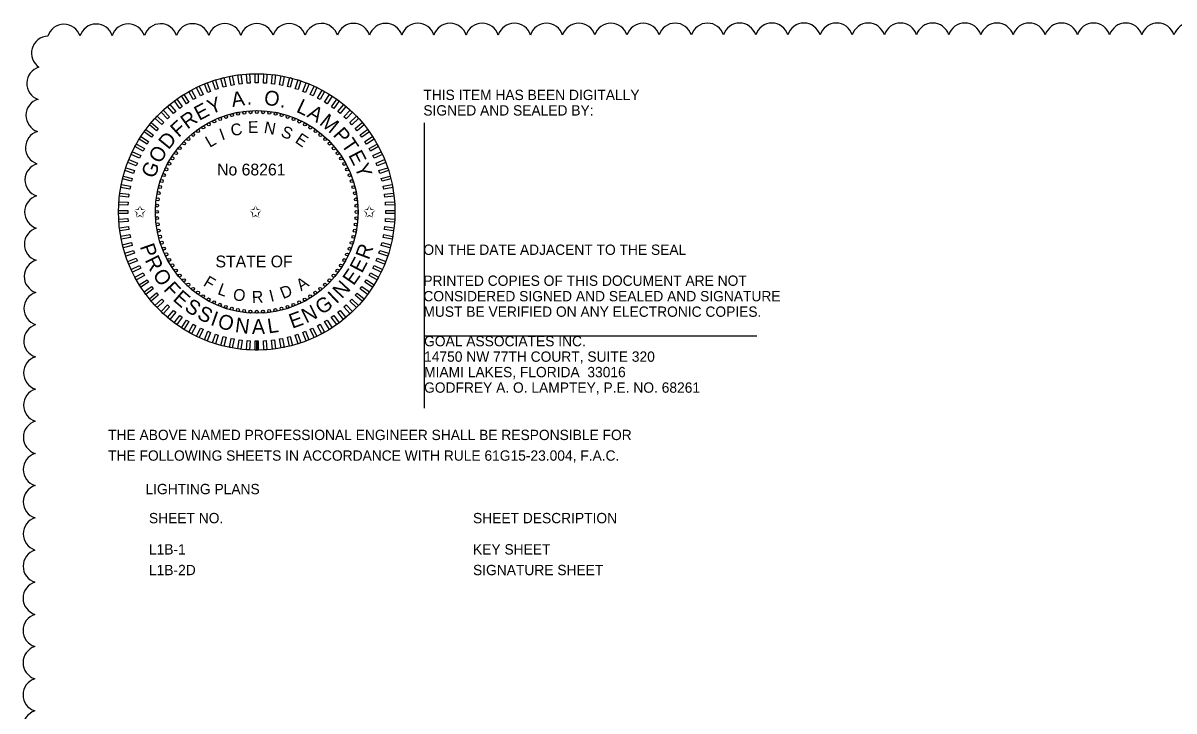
# Model space of a CAD drawing. Extents: x -811.2 to -795, y -2307.6 to -2235.1.
# Drawn here: x -811.08 to -803.27, y -2289.48 to -2284.82 of the extents above; entities that cross this region are included whole.
import ezdxf

# ---------------------------------------------------------------- set-up
doc = ezdxf.new("R2010")
doc.units = 0
for name, color, linetype in [('AdhocPoint_dp', 7, 'Continuous'), ('Cloud_dp', 7, 'Continuous'), ('Logo_dp', 7, 'Continuous'), ('TeleMisc', 7, 'Continuous'), ('TextDetails', 7, 'Continuous'), ('TextMisc', 7, 'Continuous')]:
    doc.layers.add(name, color=color, linetype=linetype)

msp = doc.modelspace()

# ---------------------------------------------------------------- linework, layer by layer
at = {"layer": 'AdhocPoint_dp'}
for p, q in [((-808.3546, -2285.4958), (-808.3546, -2287.4306)), ((-808.3546, -2286.9406), (-806.0979, -2286.9406))]:
    msp.add_line(p, q, dxfattribs=at)
at = {"layer": 'Cloud_dp'}
for centre, radius, start, end in [((-810.7982, -2284.9413), 0.1145, 18.05658, 163.05658), ((-810.58, -2284.9396), 0.1145, 17.79982, 162.79982), ((-810.3617, -2284.9386), 0.1145, 17.71875, 162.71875), ((-810.1434, -2284.9379), 0.1145, 17.67426, 162.67426), ((-809.9251, -2284.9373), 0.1145, 17.64508, 162.64508), ((-809.7068, -2284.9368), 0.1145, 17.62402, 162.62402), ((-809.4885, -2284.9363), 0.1145, 17.60791, 162.60791), ((-809.2701, -2284.9359), 0.1145, 17.59506, 162.59506), ((-809.0518, -2284.9356), 0.1145, 17.5845, 162.5845), ((-808.8335, -2284.9353), 0.1145, 17.57563, 162.57563), ((-808.6152, -2284.935), 0.1145, 17.56803, 162.56803), ((-808.3969, -2284.9348), 0.1145, 17.56143, 162.56143), ((-808.1786, -2284.9345), 0.1145, 17.55563, 162.55563), ((-807.9602, -2284.9343), 0.1145, 17.55047, 162.55047), ((-807.7419, -2284.9342), 0.1145, 17.54585, 162.54585), ((-807.5236, -2284.934), 0.1145, 17.54168, 162.54168), ((-807.3053, -2284.9338), 0.1145, 17.53789, 162.53789), ((-807.087, -2284.9337), 0.1145, 17.53443, 162.53443), ((-806.8686, -2284.9336), 0.1145, 17.53125, 162.53125), ((-806.6503, -2284.9335), 0.1145, 17.52832, 162.52832), ((-806.432, -2284.9334), 0.1145, 17.52559, 162.52559), ((-806.2137, -2284.9333), 0.1145, 17.52306, 162.52306), ((-805.9953, -2284.9332), 0.1145, 17.5207, 162.5207), ((-805.777, -2284.9331), 0.1145, 17.51849, 162.51849), ((-805.5587, -2284.933), 0.1145, 17.51642, 162.51642), ((-805.3404, -2284.933), 0.1145, 17.51447, 162.51447), ((-805.1221, -2284.9329), 0.1145, 17.51263, 162.51263), ((-804.9037, -2284.9329), 0.1145, 17.51089, 162.51089), ((-804.6854, -2284.9329), 0.1145, 17.50924, 162.50924), ((-804.4671, -2284.9328), 0.1145, 17.50767, 162.50767), ((-804.2488, -2284.9328), 0.1145, 17.50619, 162.50619), ((-804.0304, -2284.9328), 0.1145, 17.50477, 162.50477), ((-803.8121, -2284.9328), 0.1145, 17.50342, 162.50342), ((-803.5938, -2284.9327), 0.1145, 17.50213, 162.50213), ((-803.3755, -2284.9327), 0.1145, 17.5009, 162.5009), ((-803.1571, -2284.9327), 0.1145, 17.50004, 162.50004), ((-810.9047, -2285.0222), 0.1144, 91.47713, 236.47713), ((-810.9365, -2285.2277), 0.1145, 105.90805, 250.90805), ((-810.9416, -2285.4456), 0.1145, 106.41676, 251.41676), ((-810.9452, -2285.6638), 0.1145, 106.67623, 251.67623), ((-810.9481, -2285.882), 0.1145, 106.84098, 251.84098), ((-810.9504, -2286.1002), 0.1145, 106.95758, 251.95758), ((-810.9523, -2286.3185), 0.1145, 107.04572, 252.04572), ((-810.9539, -2286.5368), 0.1145, 107.11538, 252.11538), ((-810.9552, -2286.755), 0.1145, 107.17224, 252.17224), ((-810.9564, -2286.9733), 0.1145, 107.21979, 252.21979), ((-810.9574, -2287.1916), 0.1145, 107.26033, 252.26033), ((-810.9582, -2287.4099), 0.1145, 107.29543, 252.29543), ((-810.9589, -2287.6282), 0.1145, 107.3262, 252.3262), ((-810.9595, -2287.8465), 0.1145, 107.35348, 252.35348), ((-810.96, -2288.0649), 0.1145, 107.37786, 252.37786), ((-810.9605, -2288.2832), 0.1145, 107.39984, 252.39984), ((-810.9608, -2288.5015), 0.1145, 107.41978, 252.41978), ((-810.9611, -2288.7198), 0.1145, 107.43798, 252.43798), ((-810.9613, -2288.9381), 0.1145, 107.45468, 252.45468), ((-810.9614, -2289.1564), 0.1145, 107.47007, 252.47007), ((-810.9615, -2289.3747), 0.1145, 107.48432, 252.48432), ((-810.9616, -2289.593), 0.1145, 107.49902, 252.49902)]:
    msp.add_arc(centre, radius, start, end, dxfattribs=at)
at = {"layer": 'TextDetails'}
for radius in [0.9375, 0.6875]:
    msp.add_circle((-809.4901, -2286.0992), radius, dxfattribs=at)
at = {"layer": 'TextMisc'}
for p, q in [((-809.5001, -2287.0368), (-809.5003, -2286.9743)), ((-809.4901, -2287.0367), (-809.4903, -2286.9742)), ((-809.4801, -2287.0367), (-809.4803, -2286.9742))]:
    msp.add_line(p, q, dxfattribs=at)
for points in [[(-809.6979, -2285.2492), (-809.7174, -2285.2542), (-809.7329, -2285.1937), (-809.7134, -2285.1887)], [(-809.6441, -2285.2378), (-809.6639, -2285.2416), (-809.6756, -2285.1803), (-809.6558, -2285.1765)], [(-809.5897, -2285.2298), (-809.6097, -2285.2324), (-809.6175, -2285.1704), (-809.5975, -2285.1679)], [(-809.5349, -2285.2253), (-809.555, -2285.2266), (-809.559, -2285.1643), (-809.5388, -2285.163)], [(-809.4799, -2285.2242), (-809.5001, -2285.2242), (-809.5001, -2285.1618), (-809.4799, -2285.1618)], [(-809.425, -2285.2266), (-809.4452, -2285.2253), (-809.4412, -2285.163), (-809.4211, -2285.1643)], [(-809.3703, -2285.2324), (-809.3904, -2285.2299), (-809.3825, -2285.1679), (-809.3625, -2285.1704)], [(-809.3162, -2285.2416), (-809.336, -2285.2378), (-809.3243, -2285.1765), (-809.3045, -2285.1803)], [(-809.2626, -2285.2542), (-809.2822, -2285.2492), (-809.2667, -2285.1887), (-809.2471, -2285.1938)], [(-809.9027, -2285.3275), (-809.9204, -2285.3373), (-809.9505, -2285.2826), (-809.9328, -2285.2728)], [(-809.8535, -2285.3032), (-809.8717, -2285.3118), (-809.8983, -2285.2553), (-809.8801, -2285.2467)], [(-809.8028, -2285.2819), (-809.8215, -2285.2893), (-809.8445, -2285.2313), (-809.8258, -2285.2239)], [(-809.7508, -2285.2639), (-809.77, -2285.2701), (-809.7893, -2285.2108), (-809.7701, -2285.2045)], [(-809.21, -2285.2702), (-809.2292, -2285.264), (-809.2099, -2285.2046), (-809.1907, -2285.2108)], [(-809.1585, -2285.2894), (-809.1773, -2285.282), (-809.1543, -2285.2239), (-809.1355, -2285.2314)], [(-809.1083, -2285.3118), (-809.1266, -2285.3032), (-809.1, -2285.2467), (-809.0817, -2285.2553)], [(-809.0596, -2285.3374), (-809.0773, -2285.3276), (-809.0473, -2285.2729), (-809.0296, -2285.2826)], [(-809.9962, -2285.3853), (-810.0125, -2285.3972), (-810.0492, -2285.3467), (-810.0329, -2285.3348)], [(-809.9504, -2285.355), (-809.9674, -2285.3658), (-810.0009, -2285.3131), (-809.9838, -2285.3023)], [(-809.0127, -2285.3659), (-809.0297, -2285.3551), (-808.9962, -2285.3024), (-808.9792, -2285.3132)], [(-808.9676, -2285.3973), (-808.9839, -2285.3855), (-808.9472, -2285.3349), (-808.9308, -2285.3468)], [(-810.0817, -2285.4544), (-810.0964, -2285.4682), (-810.1392, -2285.4227), (-810.1244, -2285.4089)], [(-810.04, -2285.4185), (-810.0556, -2285.4314), (-810.0954, -2285.3833), (-810.0798, -2285.3704)], [(-808.9245, -2285.4315), (-808.9401, -2285.4187), (-808.9003, -2285.3705), (-808.8847, -2285.3834)], [(-808.8837, -2285.4684), (-808.8984, -2285.4545), (-808.8557, -2285.409), (-808.841, -2285.4228)], [(-810.1579, -2285.5336), (-810.1707, -2285.5492), (-810.2188, -2285.5094), (-810.206, -2285.4938)], [(-810.121, -2285.4928), (-810.1348, -2285.5075), (-810.1804, -2285.4648), (-810.1665, -2285.4501)], [(-808.8453, -2285.5077), (-808.8591, -2285.493), (-808.8136, -2285.4502), (-808.7998, -2285.4649)], [(-808.8094, -2285.5493), (-808.8223, -2285.5338), (-808.7742, -2285.494), (-808.7613, -2285.5095)], [(-810.192, -2285.5767), (-810.2039, -2285.593), (-810.2544, -2285.5563), (-810.2426, -2285.54)], [(-808.7762, -2285.5932), (-808.7881, -2285.5768), (-808.7376, -2285.5401), (-808.7257, -2285.5565)], [(-810.252, -2285.6688), (-810.2617, -2285.6865), (-810.3164, -2285.6564), (-810.3067, -2285.6387)], [(-810.2235, -2285.6218), (-810.2343, -2285.6388), (-810.287, -2285.6054), (-810.2762, -2285.5883)], [(-808.7459, -2285.639), (-808.7567, -2285.6219), (-808.7039, -2285.5885), (-808.6931, -2285.6055)], [(-808.7184, -2285.6866), (-808.7281, -2285.6689), (-808.6734, -2285.6389), (-808.6637, -2285.6565)], [(-810.2775, -2285.7175), (-810.2861, -2285.7357), (-810.3426, -2285.7091), (-810.334, -2285.6909)], [(-808.694, -2285.7359), (-808.7026, -2285.7176), (-808.6461, -2285.691), (-808.6375, -2285.7093)], [(-810.3192, -2285.8192), (-810.3254, -2285.8384), (-810.3848, -2285.8191), (-810.3786, -2285.7999)], [(-810.3, -2285.7677), (-810.3074, -2285.7864), (-810.3654, -2285.7634), (-810.358, -2285.7447)], [(-808.6728, -2285.7866), (-808.6802, -2285.7678), (-808.6222, -2285.7448), (-808.6147, -2285.7636)], [(-808.6548, -2285.8385), (-808.661, -2285.8193), (-808.6016, -2285.8), (-808.5954, -2285.8192)], [(-810.3351, -2285.8718), (-810.3401, -2285.8913), (-810.4006, -2285.8758), (-810.3956, -2285.8562)], [(-808.64, -2285.8915), (-808.6451, -2285.872), (-808.5846, -2285.8564), (-808.5796, -2285.876)], [(-810.357, -2285.9795), (-810.3595, -2285.9995), (-810.4215, -2285.9917), (-810.4189, -2285.9716)], [(-810.3477, -2285.9253), (-810.3515, -2285.9451), (-810.4129, -2285.9334), (-810.4091, -2285.9136)], [(-808.6287, -2285.9453), (-808.6325, -2285.9255), (-808.5711, -2285.9138), (-808.5673, -2285.9336)], [(-808.6207, -2285.9997), (-808.6232, -2285.9797), (-808.5613, -2285.9718), (-808.5588, -2285.9919)], [(-810.3628, -2286.0341), (-810.3641, -2286.0543), (-810.4264, -2286.0504), (-810.4251, -2286.0302)], [(-808.6162, -2286.0545), (-808.6174, -2286.0343), (-808.5551, -2286.0304), (-808.5539, -2286.0505)], [(-810.3652, -2286.0891), (-810.3652, -2286.1092), (-810.4276, -2286.1092), (-810.4276, -2286.0891)], [(-808.6151, -2286.1094), (-808.6151, -2286.0892), (-808.5527, -2286.0892), (-808.5527, -2286.1094)], [(-810.3641, -2286.144), (-810.3628, -2286.1642), (-810.4251, -2286.1681), (-810.4264, -2286.1479)], [(-810.3595, -2286.1988), (-810.357, -2286.2188), (-810.4189, -2286.2267), (-810.4215, -2286.2066)], [(-808.6233, -2286.219), (-808.6207, -2286.199), (-808.5588, -2286.2068), (-808.5613, -2286.2268)], [(-808.6175, -2286.1644), (-808.6162, -2286.1442), (-808.5539, -2286.1481), (-808.5551, -2286.1683)], [(-810.3516, -2286.2532), (-810.3478, -2286.273), (-810.4091, -2286.2847), (-810.4129, -2286.2649)], [(-808.6325, -2286.2732), (-808.6287, -2286.2534), (-808.5674, -2286.2651), (-808.5712, -2286.2849)], [(-810.3402, -2286.307), (-810.3352, -2286.3265), (-810.3957, -2286.3421), (-810.4007, -2286.3225)], [(-810.3255, -2286.36), (-810.3192, -2286.3792), (-810.3786, -2286.3985), (-810.3849, -2286.3793)], [(-808.6611, -2286.3793), (-808.6548, -2286.3601), (-808.5954, -2286.3794), (-808.6017, -2286.3986)], [(-808.6451, -2286.3267), (-808.6401, -2286.3072), (-808.5796, -2286.3227), (-808.5846, -2286.3423)], [(-810.3075, -2286.4119), (-810.3, -2286.4307), (-810.3581, -2286.4537), (-810.3655, -2286.4349)], [(-808.6803, -2286.4308), (-808.6729, -2286.4121), (-808.6148, -2286.4351), (-808.6222, -2286.4538)], [(-810.2862, -2286.4626), (-810.2776, -2286.4809), (-810.3341, -2286.5075), (-810.3427, -2286.4892)], [(-810.2618, -2286.5119), (-810.2521, -2286.5296), (-810.3068, -2286.5596), (-810.3165, -2286.542)], [(-808.7282, -2286.5297), (-808.7185, -2286.512), (-808.6638, -2286.5421), (-808.6735, -2286.5598)], [(-808.7027, -2286.481), (-808.6941, -2286.4628), (-808.6376, -2286.4894), (-808.6462, -2286.5076)], [(-810.2344, -2286.5595), (-810.2236, -2286.5766), (-810.2763, -2286.61), (-810.2871, -2286.593)], [(-808.7568, -2286.5767), (-808.746, -2286.5597), (-808.6932, -2286.5931), (-808.704, -2286.6102)], [(-810.204, -2286.6053), (-810.1922, -2286.6217), (-810.2427, -2286.6584), (-810.2545, -2286.642)], [(-810.1708, -2286.6492), (-810.158, -2286.6647), (-810.2061, -2286.7045), (-810.2189, -2286.689)], [(-808.8224, -2286.6649), (-808.8095, -2286.6493), (-808.7614, -2286.6891), (-808.7743, -2286.7047)], [(-808.7882, -2286.6218), (-808.7763, -2286.6055), (-808.7258, -2286.6422), (-808.7377, -2286.6585)], [(-810.135, -2286.6908), (-810.1211, -2286.7055), (-810.1667, -2286.7483), (-810.1805, -2286.7336)], [(-810.0965, -2286.7301), (-810.0818, -2286.744), (-810.1246, -2286.7895), (-810.1393, -2286.7757)], [(-808.8985, -2286.7441), (-808.8838, -2286.7303), (-808.8411, -2286.7758), (-808.8558, -2286.7896)], [(-808.8592, -2286.7057), (-808.8454, -2286.691), (-808.7999, -2286.7337), (-808.8137, -2286.7484)], [(-810.0557, -2286.767), (-810.0402, -2286.7798), (-810.08, -2286.828), (-810.0955, -2286.8151)], [(-810.0127, -2286.8012), (-809.9964, -2286.813), (-810.0331, -2286.8636), (-810.0494, -2286.8517)], [(-809.9676, -2286.8326), (-809.9505, -2286.8434), (-809.984, -2286.8961), (-810.001, -2286.8853)], [(-809.0299, -2286.8435), (-809.0128, -2286.8327), (-808.9794, -2286.8854), (-808.9964, -2286.8962)], [(-808.984, -2286.8131), (-808.9677, -2286.8013), (-808.931, -2286.8518), (-808.9473, -2286.8637)], [(-808.9402, -2286.78), (-808.9247, -2286.7671), (-808.8848, -2286.8152), (-808.9004, -2286.8281)], [(-809.9206, -2286.8611), (-809.9029, -2286.8709), (-809.933, -2286.9256), (-809.9507, -2286.9159)], [(-809.8719, -2286.8867), (-809.8536, -2286.8953), (-809.8802, -2286.9518), (-809.8985, -2286.9432)], [(-809.8217, -2286.9091), (-809.8029, -2286.9165), (-809.8259, -2286.9746), (-809.8447, -2286.9671)], [(-809.1775, -2286.9166), (-809.1587, -2286.9091), (-809.1357, -2286.9672), (-809.1545, -2286.9746)], [(-809.1268, -2286.8953), (-809.1085, -2286.8867), (-809.0819, -2286.9432), (-809.1002, -2286.9518)], [(-809.0775, -2286.8709), (-809.0598, -2286.8612), (-809.0297, -2286.9159), (-809.0474, -2286.9257)], [(-809.7702, -2286.9283), (-809.751, -2286.9345), (-809.7703, -2286.9939), (-809.7895, -2286.9877)], [(-809.7176, -2286.9443), (-809.698, -2286.9493), (-809.7136, -2287.0098), (-809.7331, -2287.0047)], [(-809.6641, -2286.9569), (-809.6443, -2286.9607), (-809.656, -2287.022), (-809.6758, -2287.0182)], [(-809.6099, -2286.9661), (-809.5899, -2286.9686), (-809.5977, -2287.0306), (-809.6177, -2287.028)], [(-809.5552, -2286.9719), (-809.5351, -2286.9732), (-809.539, -2287.0355), (-809.5592, -2287.0342)], [(-809.5003, -2286.9743), (-809.4801, -2286.9743), (-809.4801, -2287.0367), (-809.5003, -2287.0367)], [(-809.4453, -2286.9732), (-809.4252, -2286.9719), (-809.4213, -2287.0342), (-809.4414, -2287.0355)], [(-809.3906, -2286.9687), (-809.3705, -2286.9661), (-809.3627, -2287.0281), (-809.3827, -2287.0306)], [(-809.3362, -2286.9607), (-809.3163, -2286.9569), (-809.3046, -2287.0182), (-809.3245, -2287.022)], [(-809.2824, -2286.9493), (-809.2628, -2286.9443), (-809.2473, -2287.0048), (-809.2668, -2287.0098)], [(-809.2294, -2286.9346), (-809.2102, -2286.9284), (-809.1909, -2286.9877), (-809.2101, -2286.994)]]:
    msp.add_lwpolyline(points, close=True, dxfattribs=at)
for centre in [(-809.6165, -2285.4337), (-809.5745, -2285.4271), (-809.5321, -2285.4231), (-809.4896, -2285.4218), (-809.447, -2285.4232), (-809.4047, -2285.4272), (-809.3626, -2285.4339), (-809.816, -2285.5053), (-809.7781, -2285.486), (-809.739, -2285.4691), (-809.6989, -2285.4548), (-809.6581, -2285.4429), (-809.3211, -2285.4432), (-809.2802, -2285.4551), (-809.2402, -2285.4696), (-809.2012, -2285.4865), (-809.1633, -2285.5058), (-809.9215, -2285.5769), (-809.8879, -2285.5508), (-809.8527, -2285.5269), (-809.1266, -2285.5275), (-809.0915, -2285.5515), (-809.0579, -2285.5776), (-810.0118, -2285.667), (-809.9836, -2285.6351), (-809.9535, -2285.605), (-809.026, -2285.6058), (-808.9959, -2285.6359), (-808.9678, -2285.6678), (-810.0618, -2285.7358), (-810.0379, -2285.7006), (-808.9417, -2285.7015), (-808.9178, -2285.7367), (-810.1029, -2285.8103), (-810.0835, -2285.7724), (-808.8962, -2285.7734), (-808.8769, -2285.8113), (-810.1343, -2285.8894), (-810.1198, -2285.8493), (-808.86, -2285.8504), (-808.8456, -2285.8904), (-810.1555, -2285.9717), (-810.1462, -2285.9302), (-808.8338, -2285.9313), (-808.8245, -2285.9729), (-810.1662, -2286.0561), (-810.1622, -2286.0138), (-808.8179, -2286.0149), (-808.814, -2286.0573), (-810.1676, -2286.0987), (-810.1663, -2286.1412), (-808.814, -2286.1423), (-808.8127, -2286.0998), (-810.1623, -2286.1836), (-808.8181, -2286.1847), (-810.1557, -2286.2256), (-810.1464, -2286.2672), (-808.8341, -2286.2683), (-808.8248, -2286.2267), (-810.1346, -2286.3081), (-810.1202, -2286.3481), (-808.8604, -2286.3492), (-808.846, -2286.3091), (-810.1034, -2286.3872), (-810.0841, -2286.4251), (-808.8967, -2286.4261), (-808.8774, -2286.3882), (-810.0624, -2286.4618), (-810.0385, -2286.497), (-810.0125, -2286.5306), (-808.9685, -2286.5315), (-808.9424, -2286.4979), (-808.9184, -2286.4627), (-809.9844, -2286.5626), (-809.9543, -2286.5927), (-809.0268, -2286.5935), (-808.9967, -2286.5634), (-809.9224, -2286.6209), (-809.8888, -2286.647), (-809.8536, -2286.671), (-809.1276, -2286.6716), (-809.0924, -2286.6477), (-809.0587, -2286.6216), (-809.817, -2286.6926), (-809.7791, -2286.712), (-809.74, -2286.7289), (-809.7, -2286.7434), (-809.6591, -2286.7553), (-809.6176, -2286.7646), (-809.3637, -2286.7648), (-809.3222, -2286.7556), (-809.2813, -2286.7437), (-809.2413, -2286.7293), (-809.2022, -2286.7125), (-809.1642, -2286.6932), (-809.5756, -2286.7713), (-809.5332, -2286.7753), (-809.4901, -2286.7767), (-809.4481, -2286.7754), (-809.4058, -2286.7714)]:
    msp.add_circle(centre, 0.01, dxfattribs=at)

# ---------------------------------------------------------------- texts
at = {"layer": 'Logo_dp'}
for s, p in [('THIS ITEM HAS BEEN DIGITALLY', (-808.3596, -2285.3407)), ('SIGNED AND SEALED BY:', (-808.3596, -2285.4457)), ('ON THE DATE ADJACENT TO THE SEAL', (-808.3596, -2286.3907)), ('PRINTED COPIES OF THIS DOCUMENT ARE NOT ', (-808.3596, -2286.6007)), ('CONSIDERED SIGNED AND SEALED AND SIGNATURE ', (-808.3596, -2286.7057)), ('MUST BE VERIFIED ON ANY ELECTRONIC COPIES.', (-808.3596, -2286.8107)), ('GOAL ASSOCIATES INC.', (-808.3546, -2287.0106)), ('14750 NW 77TH COURT, SUITE 320', (-808.3546, -2287.1156)), ('MIAMI LAKES, FLORIDA  33016', (-808.3546, -2287.2206)), ('GODFREY A. O. LAMPTEY, P.E. NO. 68261', (-808.3546, -2287.3256)), ('THE ABOVE NAMED PROFESSIONAL ENGINEER SHALL BE RESPONSIBLE FOR ', (-810.4987, -2287.6467)), ('THE FOLLOWING SHEETS IN ACCORDANCE WITH RULE 61G15-23.004, F.A.C.', (-810.4987, -2287.7867)), ('LIGHTING PLANS', (-810.245, -2288.0137))]:
    msp.add_text(s, height=0.07, dxfattribs=at).set_placement(p)
at = {"layer": 'TeleMisc'}
for s, p in [('SHEET NO.', (-810.2215, -2288.2107)), ('SHEET DESCRIPTION', (-808.0226, -2288.2107)), ('L1B-1', (-810.2215, -2288.4229)), ('KEY SHEET', (-808.0226, -2288.4229)), ('L1B-2D', (-810.2215, -2288.5629)), ('SIGNATURE SHEET', (-808.0226, -2288.5629))]:
    msp.add_text(s, height=0.07, dxfattribs=at).set_placement(p)
at = {"layer": 'TextMisc'}
for s, height, rotation, p in [('O', 0.1, 352.18771, (-809.4449, -2285.3711)), ('Y', 0.1, 21.06329, (-809.8021, -2285.4398)), ('A', 0.1, 8.80884, (-809.6551, -2285.3886)), ('L', 0.1, 334.67271, (-809.2279, -2285.4185)), ('R', 0.1, 35.92688, (-809.9609, -2285.5419)), ('E', 0.1, 28.10553, (-809.8806, -2285.4831)), ('.', 0.1, 1.04184, (-809.5575, -2285.3729)), ('.', 0.1, 343.52684, (-809.3358, -2285.3862)), ('A', 0.1, 328.40959, (-809.1552, -2285.4512)), ('F', 0.1, 42.37723, (-810.0205, -2285.5983)), ('C', 0.08, 12.20255, (-809.6579, -2285.5876)), ('E', 0.08, 0.41861, (-809.5498, -2285.5642)), ('N', 0.08, 349.29143, (-809.4455, -2285.5627)), ('M', 0.1, 320.6426, (-809.0707, -2285.5024)), ('D', 0.1, 50.8569, (-810.0886, -2285.682)), ('L', 0.08, 30.40215, (-809.8093, -2285.6656)), ('I', 0.08, 20.01168, (-809.7258, -2285.6152)), ('S', 0.08, 337.02207, (-809.3325, -2285.5845)), ('E', 0.08, 325.86633, (-809.2358, -2285.6247)), ('P', 0.1, 311.19658, (-808.9784, -2285.5793)), ('O', 0.1, 59.51777, (-810.1446, -2285.7769)), ('T', 0.1, 304.45632, (-808.9209, -2285.643)), ('E', 0.1, 297.63152, (-808.8707, -2285.7138)), ('G', 0.1, 68.0518, (-810.1851, -2285.8776)), ('Y', 0.1, 290.58928, (-808.8281, -2285.7927)), ('P', 0.1, 289.40551, (-810.2848, -2286.3338)), ('R', 0.1, 69.5134, (-808.7299, -2286.4289)), ('R', 0.1, 296.14576, (-810.2518, -2286.4255)), ('E', 0.1, 62.47116, (-808.7761, -2286.5197)), ('O', 0.1, 303.96711, (-810.2003, -2286.5261)), ('E', 0.1, 55.42892, (-808.833, -2286.604)), ('F', 0.1, 312.62798, (-810.1279, -2286.6282)), ('F', 0.08, 328.72408, (-809.8582, -2286.5958)), ('L', 0.08, 339.29159, (-809.7609, -2286.6549)), ('D', 0.08, 22.01279, (-809.312, -2286.6912)), ('A', 0.08, 34.49917, (-809.1883, -2286.6387)), ('N', 0.1, 47.17876, (-808.9123, -2286.6931)), ('E', 0.1, 319.07833, (-810.0645, -2286.6965)), ('O', 0.08, 349.68206, (-809.6562, -2286.6946)), ('R', 0.08, 2.33977, (-809.5217, -2286.7166)), ('I', 0.08, 14.20366, (-809.3941, -2286.7099)), ('G', 0.1, 35.11153, (-809.0492, -2286.8008)), ('I', 0.1, 43.64556, (-808.9499, -2286.7276)), ('S', 0.1, 326.12056, (-809.9869, -2286.7624)), ('S', 0.1, 333.193, (-809.9015, -2286.8185)), ('N', 0.1, 26.86136, (-809.1544, -2286.8568)), ('I', 0.1, 340.26543, (-809.8098, -2286.8637)), ('O', 0.1, 343.79863, (-809.7621, -2286.8819)), ('N', 0.1, 352.45949, (-809.6411, -2286.914)), ('A', 0.1, 0.70966, (-809.5227, -2286.9272)), ('L', 0.1, 8.47665, (-809.4105, -2286.924)), ('E', 0.1, 19.81912, (-809.2498, -2286.8922))]:
    msp.add_text(s, height=height, rotation=rotation, dxfattribs=at).set_placement(p)
for s, p in [('No 68261', (-809.7591, -2285.852)), ('✩', (-810.3251, -2286.1372)), ('✩', (-809.5404, -2286.1372)), ('✩', (-808.7685, -2286.1372)), ('STATE OF', (-809.7698, -2286.4754))]:
    msp.add_text(s, height=0.08, dxfattribs=at).set_placement(p)

doc.saveas('drawing.dxf')
